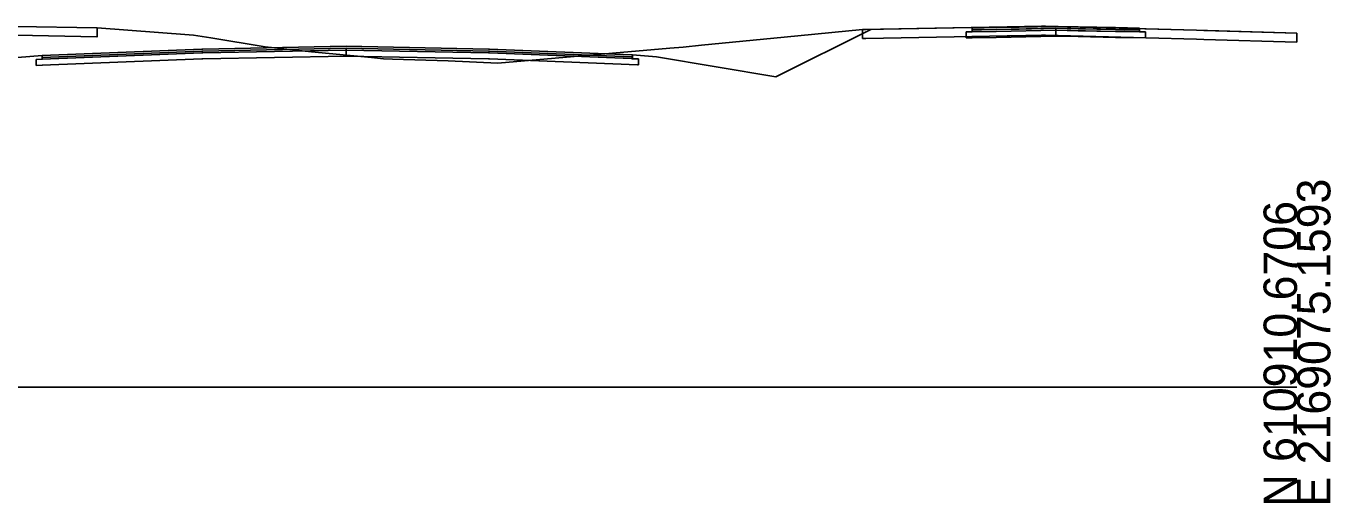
# Model space of a CAD drawing. Extents: x -26 to 1303, y -3010 to 12038.
# Drawn here: x 1193.6 to 1302.8, y 7990.3 to 8030.3 of the extents above; entities that cross this region are included whole.
import ezdxf

# ---------------------------------------------------------------- set-up
doc = ezdxf.new("R2010")
doc.units = 0
for name, color, linetype in [('RD_GPK_XS_Cell', 7, 'Continuous'), ('RD_XS_Base', 7, 'Continuous'), ('RD_XS_ExGround', 7, 'Continuous'), ('RD_XS_ExPaveRet', 7, 'Continuous'), ('RD_XS_Greenside', 7, 'Continuous'), ('RD_XS_Pave', 7, 'Continuous'), ('RD_XS_PaveOvlay_CP', 7, 'Continuous'), ('RD_XS_TieSlope', 7, 'Continuous')]:
    doc.layers.add(name, color=color, linetype=linetype)

msp = doc.modelspace()

# ---------------------------------------------------------------- linework, layer by layer
at = {"layer": 'RD_GPK_XS_Cell'}
msp.add_line((1150, 8000), (1300, 8000), dxfattribs=at)
at = {"layer": 'RD_XS_Base'}
for p, q in [((1274.81, 8029.82), (1279.81, 8029.92)), ((1279.81, 8029.98), (1279.81, 8030.08)), ((1279.81, 8030.08), (1279.81, 8029.83)), ((1279.81, 8029.92), (1279.81, 8029.98)), ((1281.66, 8029.88), (1279.81, 8029.92)), ((1279.81, 8029.92), (1279.81, 8029.42)), ((1272.3, 8029.77), (1272.8, 8029.78)), ((1272.3, 8029.27), (1272.3, 8029.77)), ((1272.8, 8029.28), (1272.3, 8029.27)), ((1272.8, 8029.78), (1274.81, 8029.82)), ((1274.81, 8029.32), (1272.8, 8029.28)), ((1279.81, 8029.42), (1274.81, 8029.32)), ((1279.81, 8029.83), (1279.81, 8029.42)), ((1279.81, 8029.42), (1281.66, 8029.38)), ((1284.81, 8029.82), (1281.66, 8029.88)), ((1281.66, 8029.38), (1284.81, 8029.32)), ((1285.53, 8029.8), (1284.81, 8029.82)), ((1284.81, 8029.32), (1285.71, 8029.3)), ((1286.81, 8029.78), (1285.53, 8029.8)), ((1285.71, 8029.3), (1287.31, 8029.27)), ((1286.99, 8029.77), (1286.81, 8029.78)), ((1287.31, 8029.77), (1286.99, 8029.77)), ((1287.31, 8029.59), (1287.31, 8029.77)), ((1287.31, 8029.27), (1287.31, 8029.59)), ((1208.27, 8028.01), (1194.9, 8027.48)), ((1208.36, 8028.01), (1208.27, 8028.01)), ((1220.36, 8028.25), (1208.36, 8028.01)), ((1208.36, 8027.51), (1220.36, 8027.75)), ((1220.36, 8028.25), (1220.36, 8028.41)), ((1220.36, 8028.41), (1220.36, 8027.76)), ((1220.36, 8027.75), (1220.36, 8028.25)), ((1220.36, 8028.25), (1220.36, 8028.25)), ((1220.36, 8028.25), (1220.36, 8028.25)), ((1232.28, 8028.01), (1220.36, 8028.25)), ((1220.36, 8028.25), (1220.36, 8028.25)), ((1220.36, 8027.76), (1220.36, 8027.75)), ((1220.36, 8027.75), (1220.36, 8027.75)), ((1220.36, 8027.75), (1232.28, 8027.51)), ((1232.36, 8028.01), (1232.28, 8028.01)), ((1244.27, 8027.54), (1232.36, 8028.01)), ((1194.9, 8027.48), (1194.4, 8027.46)), ((1194.4, 8027.46), (1194.4, 8027.46)), ((1194.4, 8027.46), (1194.4, 8026.96)), ((1194.4, 8026.96), (1194.9, 8026.98)), ((1194.4, 8026.96), (1194.4, 8026.96)), ((1194.4, 8026.96), (1194.4, 8026.96)), ((1194.9, 8026.98), (1208.27, 8027.51)), ((1194.93, 8027.48), (1194.9, 8027.48)), ((1194.9, 8026.98), (1194.93, 8026.98)), ((1208.27, 8027.51), (1208.36, 8027.51)), ((1232.28, 8027.51), (1232.36, 8027.51)), ((1232.36, 8027.51), (1244.76, 8027.02)), ((1244.36, 8027.53), (1244.27, 8027.54)), ((1244.86, 8027.51), (1244.36, 8027.53)), ((1244.76, 8027.02), (1244.86, 8027.01)), ((1244.86, 8027.02), (1244.86, 8027.51)), ((1244.86, 8027.51), (1244.86, 8027.51)), ((1244.86, 8027.01), (1244.86, 8027.02))]:
    msp.add_line(p, q, dxfattribs=at)
at = {"layer": 'RD_XS_ExGround'}
msp.add_lwpolyline([(1192.72, 8030.24), (1199.5, 8030.11), (1207.23, 8029.53), (1207.57, 8029.5), (1209.03, 8029.28), (1213.59, 8028.52), (1217.46, 8028.12), (1222.49, 8027.64), (1223.49, 8027.53), (1224.26, 8027.49), (1228.91, 8027.34), (1233.06, 8027.15), (1247.46, 8028.41), (1248.58, 8028.5), (1250.13, 8028.66), (1257.05, 8029.33), (1263.62, 8029.98), (1275.72, 8030.21), (1278.6, 8030.26), (1291.59, 8029.91), (1300, 8029.67)], dxfattribs=at)
at = {"layer": 'RD_XS_ExPaveRet'}
for p, q in [((1278.93, 8030.26), (1278.6, 8030.26)), ((1300, 8029.67), (1300, 8028.92)), ((1300, 8028.92), (1300, 8029.67))]:
    msp.add_line(p, q, dxfattribs=at)
for points in [[(1161.99, 8029.65), (1161.99, 8028.9), (1167.6, 8029.09), (1183.9, 8029.64), (1192.72, 8029.49), (1199.5, 8029.36), (1199.5, 8029.36), (1199.5, 8030.11), (1199.5, 8030.11), (1192.72, 8030.24)], [(1192.72, 8030.24), (1199.5, 8030.11), (1199.5, 8030.11)], [(1199.5, 8030.11), (1199.5, 8029.36), (1199.5, 8029.36), (1199.5, 8029.36), (1192.72, 8029.49)], [(1300, 8028.92), (1292.21, 8029.14), (1291.59, 8029.16), (1278.93, 8029.51), (1278.6, 8029.51), (1275.98, 8029.46), (1275.72, 8029.46), (1263.89, 8029.23), (1263.62, 8029.23), (1263.62, 8029.23), (1263.62, 8029.23), (1263.62, 8029.25), (1263.62, 8029.98), (1263.62, 8029.98), (1263.62, 8029.98), (1263.89, 8029.98), (1275.72, 8030.21), (1275.98, 8030.21), (1278.6, 8030.26), (1278.93, 8030.26), (1291.59, 8029.91), (1292.21, 8029.89)], [(1278.6, 8030.26), (1275.98, 8030.21), (1275.72, 8030.21), (1263.89, 8029.98), (1263.62, 8029.98), (1263.62, 8029.98)], [(1263.62, 8029.98), (1263.62, 8029.25), (1263.62, 8029.23), (1263.62, 8029.23), (1263.89, 8029.23), (1275.72, 8029.46), (1275.98, 8029.46), (1278.6, 8029.51), (1278.93, 8029.51), (1291.59, 8029.16), (1292.21, 8029.14), (1300, 8028.92)], [(1300, 8029.67), (1292.21, 8029.89), (1291.59, 8029.91), (1278.93, 8030.26)], [(1292.21, 8029.89), (1300, 8029.67)]]:
    msp.add_lwpolyline(points, dxfattribs=at)
at = {"layer": 'RD_XS_Greenside'}
for p, q in [((1256.36, 8026.02), (1264.3, 8029.99)), ((1246.36, 8027.69), (1256.36, 8026.02))]:
    msp.add_line(p, q, dxfattribs=at)
at = {"layer": 'RD_XS_Pave'}
for p, q in [((1273.59, 8030.11), (1272.8, 8030.1)), ((1272.8, 8030.1), (1272.8, 8030)), ((1272.8, 8030), (1272.8, 8029.94)), ((1274.81, 8029.98), (1272.8, 8029.94)), ((1272.8, 8029.94), (1273.59, 8029.95)), ((1272.8, 8029.94), (1272.8, 8029.78)), ((1274.81, 8030.14), (1273.59, 8030.11)), ((1273.59, 8029.95), (1274.81, 8029.98)), ((1276.73, 8030.18), (1274.81, 8030.14)), ((1279.81, 8030.08), (1274.81, 8029.98)), ((1274.81, 8029.98), (1276.73, 8030.02)), ((1274.81, 8029.82), (1279.81, 8029.92)), ((1279.81, 8030.24), (1276.73, 8030.18)), ((1276.73, 8030.02), (1279.81, 8030.08)), ((1281.66, 8030.2), (1279.81, 8030.24)), ((1279.81, 8030.08), (1281.66, 8030.04)), ((1284.81, 8029.98), (1279.81, 8030.08)), ((1279.81, 8030.08), (1279.81, 8029.92)), ((1279.81, 8029.92), (1279.81, 8030.08)), ((1279.81, 8029.92), (1284.81, 8029.82)), ((1284.81, 8030.14), (1281.66, 8030.2)), ((1281.66, 8030.04), (1284.81, 8029.98)), ((1285.53, 8030.12), (1284.81, 8030.14)), ((1284.81, 8029.98), (1285.53, 8029.96)), ((1286.81, 8029.94), (1284.81, 8029.98)), ((1286.81, 8030.1), (1285.53, 8030.12)), ((1285.53, 8029.96), (1286.81, 8029.94)), ((1286.81, 8029.99), (1286.81, 8030.1)), ((1286.81, 8029.94), (1286.81, 8029.99)), ((1286.81, 8029.78), (1286.81, 8029.94)), ((1272.8, 8029.78), (1274.81, 8029.82)), ((1284.81, 8029.82), (1286.81, 8029.78)), ((1208.27, 8028.33), (1194.9, 8027.79)), ((1208.27, 8028.17), (1194.9, 8027.63)), ((1194.9, 8027.63), (1208.27, 8028.17)), ((1194.9, 8027.48), (1208.27, 8028.01)), ((1194.93, 8027.79), (1194.9, 8027.79)), ((1194.9, 8027.79), (1194.9, 8027.63)), ((1208.36, 8028.33), (1208.27, 8028.33)), ((1208.36, 8028.17), (1208.27, 8028.17)), ((1208.27, 8028.17), (1208.36, 8028.17)), ((1208.27, 8028.01), (1208.36, 8028.01)), ((1220.36, 8028.57), (1208.36, 8028.33)), ((1220.36, 8028.41), (1208.36, 8028.17)), ((1208.36, 8028.17), (1220.36, 8028.41)), ((1208.36, 8028.01), (1220.36, 8028.25)), ((1232.28, 8028.33), (1220.36, 8028.57)), ((1220.36, 8028.25), (1220.36, 8028.41)), ((1220.36, 8028.41), (1232.28, 8028.17)), ((1232.28, 8028.17), (1220.36, 8028.41)), ((1220.36, 8028.41), (1220.36, 8028.41)), ((1220.36, 8028.41), (1220.36, 8028.41)), ((1220.36, 8028.41), (1220.36, 8028.25)), ((1220.36, 8028.25), (1220.36, 8028.25)), ((1220.36, 8028.25), (1220.36, 8028.25)), ((1220.36, 8028.25), (1220.36, 8028.25)), ((1220.36, 8028.25), (1220.36, 8028.25)), ((1220.36, 8028.25), (1232.28, 8028.01)), ((1232.36, 8028.33), (1232.28, 8028.33)), ((1232.28, 8028.17), (1232.36, 8028.17)), ((1232.36, 8028.17), (1232.28, 8028.17)), ((1232.28, 8028.01), (1232.36, 8028.01)), ((1244.27, 8027.85), (1232.36, 8028.33)), ((1232.36, 8028.17), (1244.27, 8027.69)), ((1244.27, 8027.69), (1232.36, 8028.17)), ((1232.36, 8028.01), (1244.27, 8027.54)), ((1244.36, 8027.85), (1244.27, 8027.85)), ((1244.36, 8027.69), (1244.36, 8027.85)), ((1194.93, 8027.64), (1194.9, 8027.63)), ((1194.9, 8027.63), (1194.93, 8027.64)), ((1194.9, 8027.63), (1194.9, 8027.48)), ((1194.9, 8027.63), (1194.9, 8027.63)), ((1194.9, 8027.48), (1194.9, 8027.48)), ((1194.9, 8027.48), (1194.93, 8027.48)), ((1244.27, 8027.69), (1244.36, 8027.69)), ((1244.36, 8027.69), (1244.27, 8027.69)), ((1244.27, 8027.54), (1244.36, 8027.53)), ((1244.36, 8027.69), (1244.36, 8027.69)), ((1244.36, 8027.53), (1244.36, 8027.69)), ((1244.36, 8027.53), (1244.36, 8027.53))]:
    msp.add_line(p, q, dxfattribs=at)
at = {"layer": 'RD_XS_PaveOvlay_CP'}
for p, q in [((1272.8, 8030.1), (1274.81, 8030.14)), ((1274.81, 8030.14), (1279.81, 8030.24)), ((1279.81, 8030.24), (1284.81, 8030.14)), ((1284.81, 8030.14), (1286.81, 8030.1)), ((1208.27, 8028.33), (1194.9, 8027.79)), ((1194.93, 8027.79), (1194.9, 8027.79)), ((1208.36, 8028.33), (1208.27, 8028.33)), ((1220.36, 8028.57), (1208.36, 8028.33)), ((1232.28, 8028.33), (1220.36, 8028.57)), ((1232.36, 8028.33), (1232.28, 8028.33)), ((1244.27, 8027.85), (1232.36, 8028.33)), ((1244.36, 8027.85), (1244.27, 8027.85))]:
    msp.add_line(p, q, dxfattribs=at)
at = {"layer": 'RD_XS_TieSlope'}
for p, q in [((1194.9, 8027.79), (1188.9, 8027.31)), ((1244.36, 8027.85), (1246.36, 8027.69))]:
    msp.add_line(p, q, dxfattribs=at)

# ---------------------------------------------------------------- texts
at = {"layer": 'RD_GPK_XS_Cell'}
for s, p in [('E 2169075.1593', (1302.8, 7990)), ('N 610910.6706', (1300, 7990))]:
    msp.add_text(s, height=2.8, rotation=90, dxfattribs=at).set_placement(p)

doc.saveas('drawing.dxf')
